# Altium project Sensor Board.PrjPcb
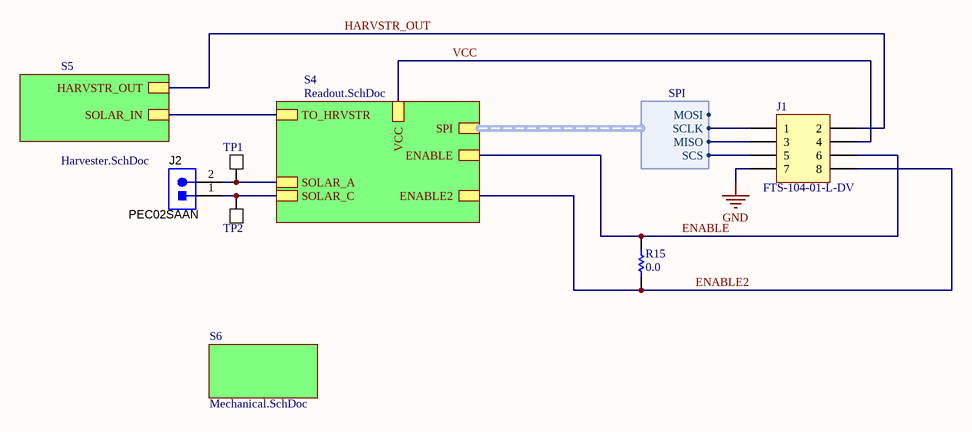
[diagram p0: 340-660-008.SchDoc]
ASSM_PN: Set In Variant; BOM_REV: 1.0.0; DOC_NUM: 340-660-008; DOC_REV: 1.0.0; PCB_PN: 21000-1008
4 sheets, 42 parts. Net scope: hierarchical (ports join the sheet entries above them; power ports are global).
Board file: 340-660-008.PcbDoc
Sheets:
  340-660-008.SchDoc
    S4 = Readout.SchDoc
    S5 = Harvester.SchDoc
    S6 = Mechanical.SchDoc

## Sheet 340-660-008.SchDoc
size A; SheetNumber: 1; SheetTotal: 4

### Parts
J1  FTS-104-01-L-DV  [CONN_SAMTEC_FTS-104-01-L-DV]
J2  PEC02SAAN  [CONN_PEC02SAAN]
R15  value 0.0  [0402_Short]  (net tie, no BOM)
TP1  TEST POINT  [TPSMTPAD]  (value not drawn)  (no BOM)
TP2  TEST POINT  [TPSMTPAD]  (value not drawn)  (no BOM)

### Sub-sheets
S4 = Readout.SchDoc: SPI (harness SPI), SOLAR_A, TO_HRVSTR, ENABLE, VCC, SOLAR_C, ENABLE2
S5 = Harvester.SchDoc: HARVSTR_OUT, SOLAR_IN
S6 = Mechanical.SchDoc: no entries

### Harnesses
SPI: MISO, MOSI, SCLK, SCS

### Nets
GND: J1.7
ENABLE: J1.6 R15.2 ; sheet S4/ENABLE
ENABLE2: J1.8 R15.1 ; sheet S4/ENABLE2
HARVSTR_OUT: J1.2 ; sheet S5/HARVSTR_OUT
SOLAR_A: J2.2 TP1.1(A) ; sheet S4/SOLAR_A
SOLAR_C: J2.1 TP2.1(A) ; sheet S4/SOLAR_C
VCC: J1.4 ; sheet S4/VCC
NetD1_2: sheet S4/TO_HRVSTR, sheet S5/SOLAR_IN
NetJ1_1: J1.1 ; sheet S4/SPI.SCLK
NetJ1_3: J1.3 ; sheet S4/SPI.MISO
NetJ1_5: J1.5 ; sheet S4/SPI.SCS

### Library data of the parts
J1 = CONN_Samtec_FTS-104-01-L-DV: 2x4 0.050" Surface Mount Micro Terminal Strip; Positions: 6; Gender: MALE; Mfg: Samtec; Mfg_PN: FTS-103-01-L-DV; ADSP_PN: 03000-???
J2 = PEC02SAAN: Header, 100mil, 2x1, Tin, TH; Manufacturer: Sullins Connector Solutions; SymbolCreator: a0412235; U/M: EA
R15 = Res_0402_Short: Resistor footpring with PCB short in footprint; cut to use as regular footprint
TP1 TP2 = Test_Point_SMT: Test Point SMT

## Sheet Readout.SchDoc
size A; SheetNumber: 2; SheetTotal: 3
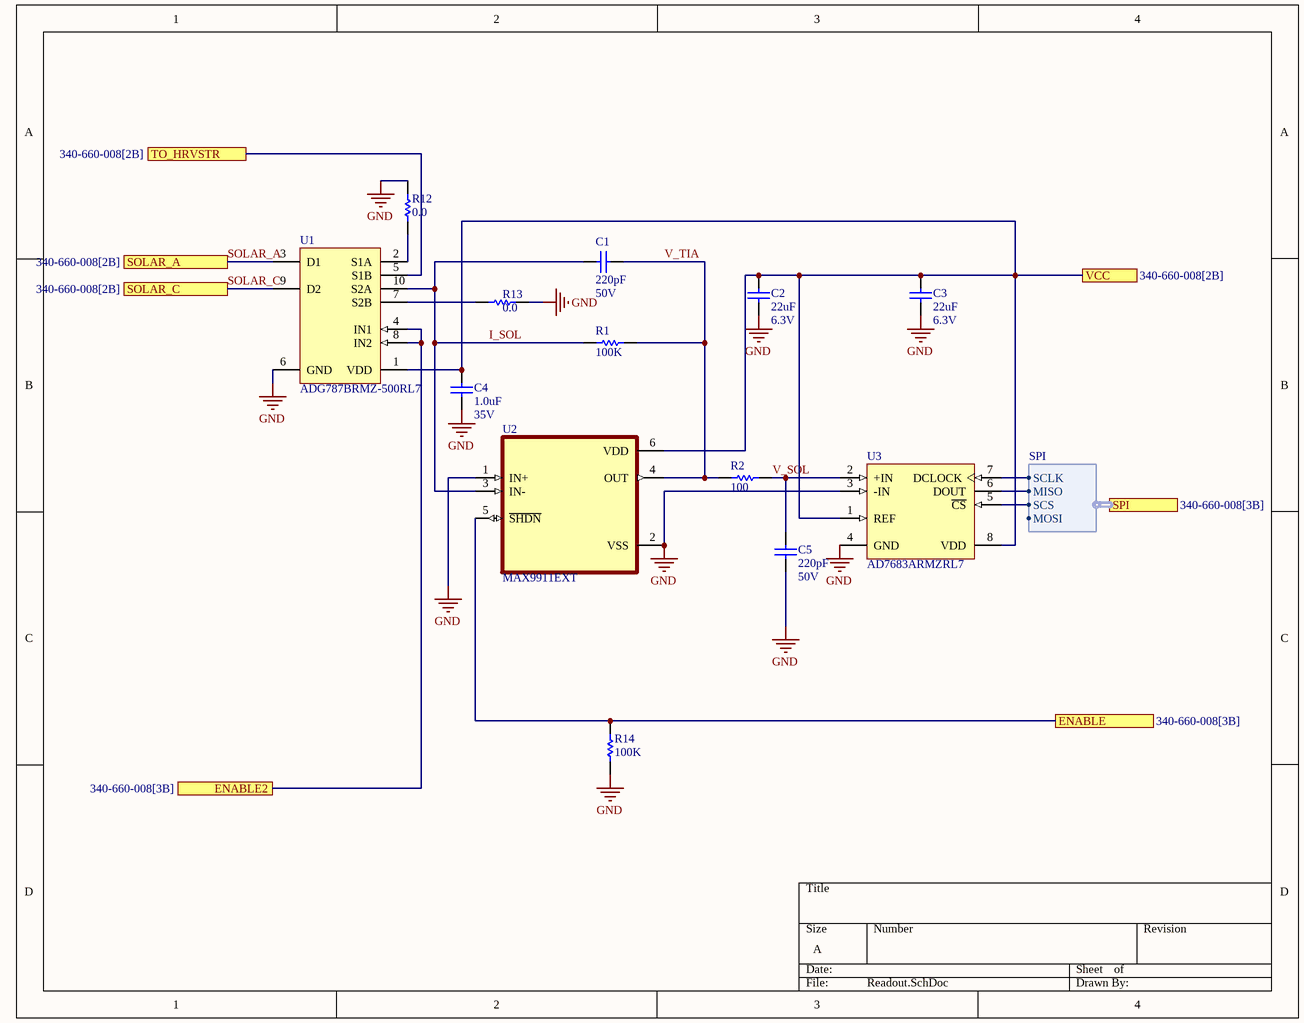
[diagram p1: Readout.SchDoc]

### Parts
C1  value 220pF  Voltage: 50V  [0402CAP]  (hidden comment: ECJ-0EC1H221J)
C2  value 22uF  Voltage: 6.3V  [0402CAP]  (hidden comment: CL05A226MQ6ZUN8)
C3  value 22uF  Voltage: 6.3V  [0402CAP]  (hidden comment: CL05A226MQ6ZUN8)
C4  value 1.0uF  Voltage: 35V  [0402CAP]  (hidden comment: C1005X5R1V105K050BC)
C5  value 220pF  Voltage: 50V  [0402CAP]  (hidden comment: ECJ-0EC1H221J)
R1  value 100K  [0402RES]  (hidden comment: RC0402FR-07100KL)
R2  value 100  [0402RES]  (hidden comment: RC0402FR-07100RL)
R12  value 0.0  [0402_Short]  (net tie, no BOM)
R13  value 0.0  [0402_Short]  (net tie, no BOM)
R14  value 100K  [0402RES]  (hidden comment: RC0402FR-07100KL)
U1  ADG787BRMZ-500RL7  [ADI-RM-10_N]
U2  MAX9911EXT  [SOT-23/6]
U3  AD7683ARMZRL7  [RM-8_M]

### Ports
ENABLE2 (see 340-660-008[3B]), ENABLE (see 340-660-008[3B]), SOLAR_A (see 340-660-008[2B]), SOLAR_C (see 340-660-008[2B]), SPI (harness SPI, see 340-660-008[3B]), TO_HRVSTR (see 340-660-008[2B]), VCC (see 340-660-008[2B])

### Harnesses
SPI: MISO, MOSI, SCLK, SCS

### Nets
GND: C2.1 C3.1 C4.1 C5.1 R12.2 R13.2 R14.2 U1.6(GND) U2.1(IN+) U2.2(VSS) U3.3(-IN) U3.4(GND)
ENABLE: R14.1 U2.5(~{SHDN}) ; port ENABLE
ENABLE2: U1.4(IN1) U1.8(IN2) ; port ENABLE2
I_SOL: C1.2 R1.2 U1.10(S2A) U2.3(IN-)
SOLAR_A: U1.3(D1) ; port SOLAR_A
SOLAR_C: U1.9(D2) ; port SOLAR_C
V_SOL: C5.2 R2.1 U3.2(+IN)
V_TIA: C1.1 R1.1 R2.2 U2.4(OUT)
VCC: C2.2 C3.2 C4.2 U1.1(VDD) U2.6(VDD) U3.1(REF) U3.8(VDD) ; port VCC
NetD1_2: U1.5(S1B) ; port TO_HRVSTR
NetJ1_1: U3.7(DCLOCK) ; port SPI.SCLK
NetJ1_3: U3.6(DOUT) ; port SPI.MISO
NetJ1_5: U3.5(~{CS}) ; port SPI.SCS
NetR12_1: R12.1 U1.2(S1A)
NetR13_1: R13.1 U1.7(S2B)

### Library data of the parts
C1 C5 = CAP_0402_220pF_NP0_50V: CAP 220PF 50V CERAMIC 0402 SMD; ADSP_PN: 01010-028; Mfg: Panasonic; Type: CAPACITOR
C2 C3 = CAP_0402_22uF_X5R_6.3V: 22µF ±20% 6.3V Ceramic Capacitor X5R 0402 (1005 Metric); ADSP_PN: 01020-158; Mfg: Samsung
C4 = CAP_0402_1uF_X5R_35V: CAP CER 1UF 35V X5R 0402; ADSP_PN: 01020-039; Mfg: TDK; Type: CAPACITOR
R1 R14 = Res_0402_100K_1%: RES 100K OHM 1/16W 1% 0402 SMD; ADSP_PN: 00100-028; Mfg: Yageo
R2 = Res_0402_100_1%_1: RES SMD 100 OHM 1% 1/16W 0402; ADSP_PN: 00100-160; Mfg: Yageo
R12 R13 = Res_0402_Short: as R15 on sheet 340-660-008
U1 = CMP-0790-00114-1: 2.5 Ohm CMOS Low Power Dual 2:1 Mux / Demux USB 1.1 Switch, -40 to 85 degC, 10-pin SOP (RM-10), Reel; Manufacturer: Analog Devices; Power Dissipation: 5.5uW; Max Pos Supply: 5.5V; Configuration: SPDT; Id, Is (ON): 50pA, 10pA; Ron (ohms): 2.5; Min Pos Supply: 1.8V
U2 = MAX9911EXT: MP: MAX9911EXT+T
U3 = CMP-0313-01716-2: Single 16-Bit PulSAR Analog-to-Digital Converter with Serial, SPI Interface, 100KSPS, -40 to +85 degC, RM-8, Pb-Free, Reel; Generic Part Number: AD7683; Manufacturer: Analog Devices; Channels: 1; Resolution (Bits): 16; Throughput Rate (SPS): 100K; Interface: Ser, SPI

## Sheet Harvester.SchDoc: Energy Harvesting
size 431 x 279 mm; Date: Not shown in title block; ApprovedBy: Not shown in title block; CheckedBy: Not shown in title block; Author: Not shown in title block; CompanyName: Not shown in title block; DrawnBy: Kelly Fernandez; Engineer: Not shown in title block; Organization: Not shown in title block; Address1: Not shown in title block; Address2: Not shown in title block; Address3: Not shown in title block; Address4: Not shown in title block; DocumentNumber: 2; Revision: Use project parameter SCH_Rev; SheetNumber: 3; SheetTotal: 3; PageSetup: Record=PageOptions¦CenterHorizontal=True¦CenterVertical=True¦PrintScale=0.62¦XCorrection=1.00¦YCorrection=1.00¦PrintKind=0¦BorderSize=5000000¦LeftOffset=0¦BottomOffset=0¦Orientation=2¦PaperLength=1000¦PaperWidth=1000¦Scale=100¦PaperSource=15¦PrintQuality=600¦MediaType=1¦DitherType=10¦PrintScaleMode=1¦PaperKind=Letter
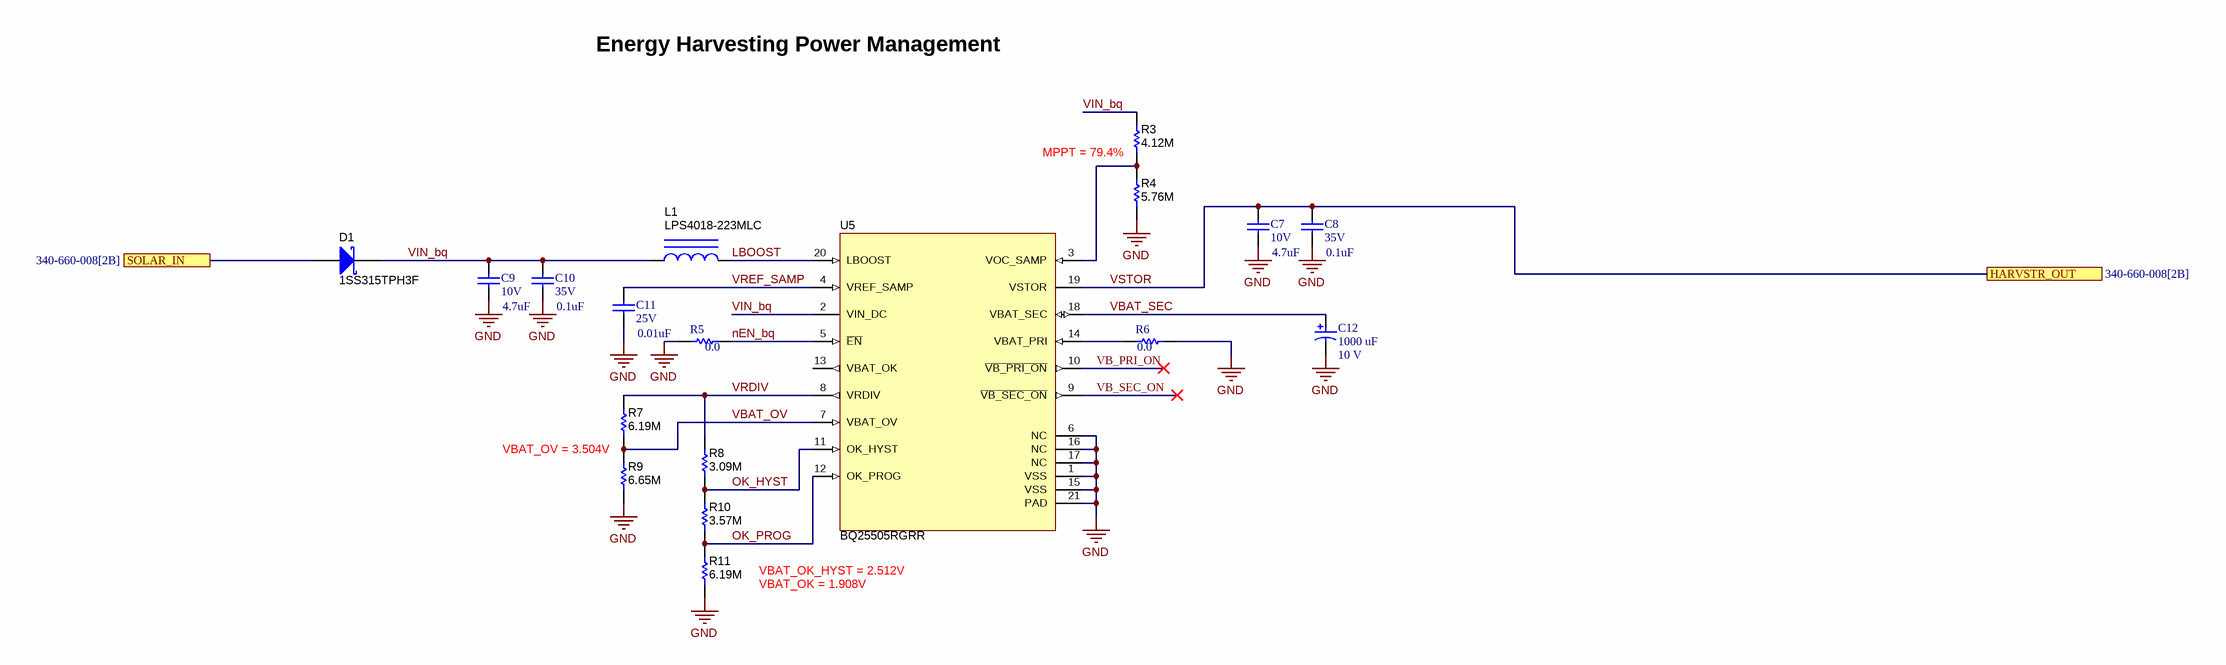
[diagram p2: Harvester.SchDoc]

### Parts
C7  value 4.7uF  Voltage: 10V  [0402CAP]  (hidden comment: GRM155R61A475MEAAD)
C8  value 0.1uF  Voltage: 35V  [0402CAP]  (hidden comment: GMK105BJ104KV-F)
C9  value 4.7uF  Voltage: 10V  [0402CAP]  (hidden comment: GRM155R61A475MEAAD)
C10  value 0.1uF  Voltage: 35V  [0402CAP]  (hidden comment: GMK105BJ104KV-F)
C11  value 0.01uF  Voltage: 25V  [0402CAP]  (hidden comment: ECJ-0EB1E103K)
C12  value 1000 uF  Voltage: 10 V  [CAP_CASEH]  (hidden comment: T523H108M010APE070)
D1  1SS315TPH3F  [sod-323]
L1  LPS4018-223MLC  [LPS4018]
R3  ValueDisplayed: 4.12M  [0402]  (hidden comment: CRCW04024M12FKED)
R4  ValueDisplayed: 5.76M  [0402]  (hidden comment: CRCW04025M76FKED)
R5  value 0.0  [0402_Short]  (net tie, no BOM)
R6  value 0.0  [0402RES]  (hidden comment: CR0402-J/-000GLF)
R7  ValueDisplayed: 6.19M  [0402]  (hidden comment: CRCW04026M19FKED)
R8  ValueDisplayed: 3.09M  [0402]  (hidden comment: CRCW04023M09FKED)
R9  ValueDisplayed: 6.65M  [0402]  (hidden comment: CRCW04026M65FKED)
R10  ValueDisplayed: 3.57M  [0402]  (hidden comment: CRCW04023M57FKED)
R11  ValueDisplayed: 6.19M  [0402]  (hidden comment: CRCW04026M19FKED)
U5  BQ25505RGRR  [RGR0020A]

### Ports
HARVSTR_OUT (see 340-660-008[2B]), SOLAR_IN (see 340-660-008[2B])

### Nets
GND: C7.2 C8.2 C9.2 C10.2 C11.2 C12.2 R4.1 R5.1 R6.1 R9.1 R11.1 U5.1(VSS) U5.6(NC) U5.15(VSS) U5.16(NC) U5.17(NC) U5.21(PAD)
LBOOST: L1.2 U5.20(LBOOST)
nEN_bq: R5.2 U5.5(~{EN})
OK_HYST: R8.1 R10.2 U5.11(OK_HYST)
OK_PROG: R10.1 R11.2 U5.12(OK_PROG)
VB_PRI_ON: U5.10(~{VB_PRI_ON})
VB_SEC_ON: U5.9(~{VB_SEC_ON})
VBAT_OV: R7.1 R9.2 U5.7(VBAT_OV)
VBAT_SEC: C12.1 U5.18(VBAT_SEC)
VIN_bq: C9.1 C10.1 D1.1(K) L1.1 R3.2 U5.2(VIN_DC)
VRDIV: R7.2 R8.2 U5.8(VRDIV)
VREF_SAMP: C11.1 U5.4(VREF_SAMP)
VSTOR: C7.1 C8.1 U5.19(VSTOR) ; port HARVSTR_OUT  [project net HARVSTR_OUT]
NetD1_2: D1.2(A) ; port SOLAR_IN
NetR3_1: R3.1 R4.2 U5.3(VOC_SAMP)
NetR6_2: R6.2 U5.14(VBAT_PRI)

Not connected (* = marked no-connect by the designer): U5 13(VBAT_OK)

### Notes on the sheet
- Energy Harvesting Power Management
- MPPT = 79.4%
- VBAT_OV = 3.504V
- VBAT_OK_HYST = 2.512V
- VBAT_OK = 1.908V

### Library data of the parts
C7 C9 = CAP_0402_4.7uF_X5R_10V: 4.7µF ±20% 10V Ceramic Capacitor X5R 0402 (1005 Metric); ADSP_PN: 01020-052; Mfg: Murata
C8 C10 = CAP_0402_0.1uF_X5R_35V: CAP CER .10UF 35V X5R 0402; ADSP_PN: 01010-054; Mfg: Taiyo Yuden; Type: CAPACITOR
C11 = CAP_0402_0.01uF_X7R_25V_2: CAP .01UF 25V CERAMIC X7R 0402; ADSP_PN: 01010-047; Mfg: Panasonic; Type: CAPACITOR
C12 = CAP_TANT_CASE_H_1000uF_10V_20%_1: 1000µF Molded Tantalum Polymer Capacitor 10V 2924 (7360 Metric) 70mOhm @ 100kHz; Tolerance Rated Capacitance: -20 to 20%; Impedance: 0.07 Ohm; Mfg: Kemet; ADSP_PN: 00120-006
D1 = 1SS315TPH3F: Diode, Schottky, 5V, 0.03A, SOD-323; Manufacturer: Toshiba; U/M: EA; Vf_V: 0.38; Value2: 0.38V; Io_A: 0.03; Vr_V: 5; TJmax_C: 125
L1 = LPS4018-223MLB: Inductor, Shielded Drum Core, Ferrite, 22 µH, 0.83 A, 0.36 ohm, SMD; Manufacturer: Coilcraft; Value: 22uH; Ind_H: 22.0E-6; ValueDisplayed: 22µH; Imax_A: 0.83; Irms: 0.9A @ 40C rise; Isat: 0.83A @ 30% inductance drop; DCR_ohm: 0.36; Value2: 0.83A
R3 = CRCW04024M12FKED: RES, 4.12 M, 1%, 0.063 W, 0402; Manufacturer: Vishay-Dale; CompType: Resistor; Value: 4.12Meg; Res_ohm: 4120000; Value_Code: 4M12; Tolerance_%: 1; Power_W: 0.063; Value2: 0.063W; VDC_V: 50; TempCo: 100 ppm/C; EIA_Code: E96; U/M: EA
R4 = CRCW04025M76FKED: RES, 5.76 M, 1%, 0.063 W, 0402; Manufacturer: Vishay-Dale; CompType: Resistor; Value: 5.76Meg; Res_ohm: 5760000; Value_Code: 5M76; Tolerance_%: 1; Power_W: 0.063; Value2: 0.063W; VDC_V: 50; TempCo: 100 ppm/C; EIA_Code: E96; U/M: EA; AEC Category: Q200
R5 = Res_0402_Short: as R15 on sheet 340-660-008
R6 = Res_0402_0.0_5%_2: RES ZERO OHM 1/10W 5% 0402 SMD; ADSP_PN: 00201-016; Mfg: Bourns
R7 R11 = CRCW04026M19FKED: RES, 6.19 M, 1%, 0.063 W, 0402; Manufacturer: Vishay-Dale; CompType: Resistor; Value: 6.19Meg; Res_ohm: 6190000; Value_Code: 6M19; Tolerance_%: 1; Power_W: 0.063; Value2: 0.063W; VDC_V: 50; TempCo: 100 ppm/C; EIA_Code: E96; U/M: EA; AEC Category: Q200
R8 = CRCW04023M09FKED: RES, 3.09 M, 1%, 0.063 W, 0402; Manufacturer: Vishay-Dale; CompType: Resistor; Value: 3.09Meg; Res_ohm: 3090000; Value_Code: 3M09; Tolerance_%: 1; Power_W: 0.063; Value2: 0.063W; VDC_V: 50; TempCo: 100 ppm/C; EIA_Code: E96; U/M: EA; AEC Category: Q200
R9 = CRCW04026M65FKED: RES, 6.65 M, 1%, 0.063 W, 0402; Manufacturer: Vishay-Dale; CompType: Resistor; Value: 6.65Meg; Res_ohm: 6650000; Value_Code: 6M65; Tolerance_%: 1; Power_W: 0.063; Value2: 0.063W; VDC_V: 50; TempCo: 100 ppm/C; EIA_Code: E96; U/M: EA; AEC Category: Q200
R10 = CRCW04023M57FKED: RES, 3.57 M, 1%, 0.063 W, 0402; Manufacturer: Vishay-Dale; CompType: Resistor; Value: 3.57Meg; Res_ohm: 3570000; Value_Code: 3M57; Tolerance_%: 1; Power_W: 0.063; Value2: 0.063W; VDC_V: 50; TempCo: 100 ppm/C; EIA_Code: E96; U/M: EA; AEC Category: Q200
U5 = BQ25505RGRR: Ultra Low Power Boost Converter with Battery Management for Energy Harvester Applications, RGR0020A; Alternate PartNumber: BQ25505RGRT; Manufacturer: Texas Instruments; SymbolCreator: a0412235; CompType: IC; U/M: EA

## Sheet Mechanical.SchDoc
size A; SheetNumber: 4; SheetTotal: 4
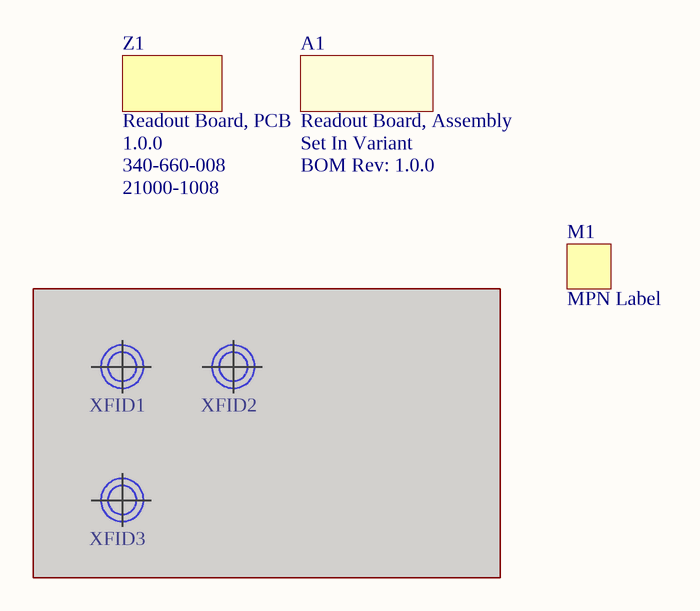
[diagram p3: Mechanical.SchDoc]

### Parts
A1  Readout Board, Assembly  BOM Rev: 1.0.0  ADSP_PN: Set In Variant  (mechanical)
M1  MPN Label  [LABEL_7x7mm]  (no BOM)
XFID1  (no value)  [FID_TOP_BOT_39]  (masked out: inside a compile mask, not in the netlist)
XFID2  (no value)  [FID_TOP_BOT_39]  (masked out: inside a compile mask, not in the netlist)
XFID3  (no value)  [FID_TOP_BOT_39]  (masked out: inside a compile mask, not in the netlist)
Z1  Readout Board, PCB  Rev: 1.0.0  DocNum: 340-660-008  ADSP_PN: 21000-1008  (mechanical)

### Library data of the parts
A1 = PCB_Assembly: DocNum: 340-660-008
M1 = Label_MPN: Serial Number Label Placeholder
XFID1-XFID3 = MOUNT_FIDUCIAL: Mounting Hole
Z1 = PCB_Rigid: RIGID PCB;  BARE

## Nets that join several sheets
GND: 340-660-008 (J1.7), Readout (12 pins), Harvester (17 pins)
ENABLE: 340-660-008 (J1.6 R15.2), Readout (R14.1 U2.5)
ENABLE2: 340-660-008 (J1.8 R15.1), Readout (U1.4 U1.8)
HARVSTR_OUT: 340-660-008 (J1.2), Harvester (C7.1 C8.1 U5.19)
NetD1_2: Readout (U1.5), Harvester (D1.2)
NetJ1_1: 340-660-008 (J1.1), Readout (U3.7)
NetJ1_3: 340-660-008 (J1.3), Readout (U3.6)
NetJ1_5: 340-660-008 (J1.5), Readout (U3.5)
SOLAR_A: 340-660-008 (J2.2 TP1.1), Readout (U1.3)
SOLAR_C: 340-660-008 (J2.1 TP2.1), Readout (U1.9)
VCC: 340-660-008 (J1.4), Readout (7 pins)

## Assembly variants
Base: not fitted J2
